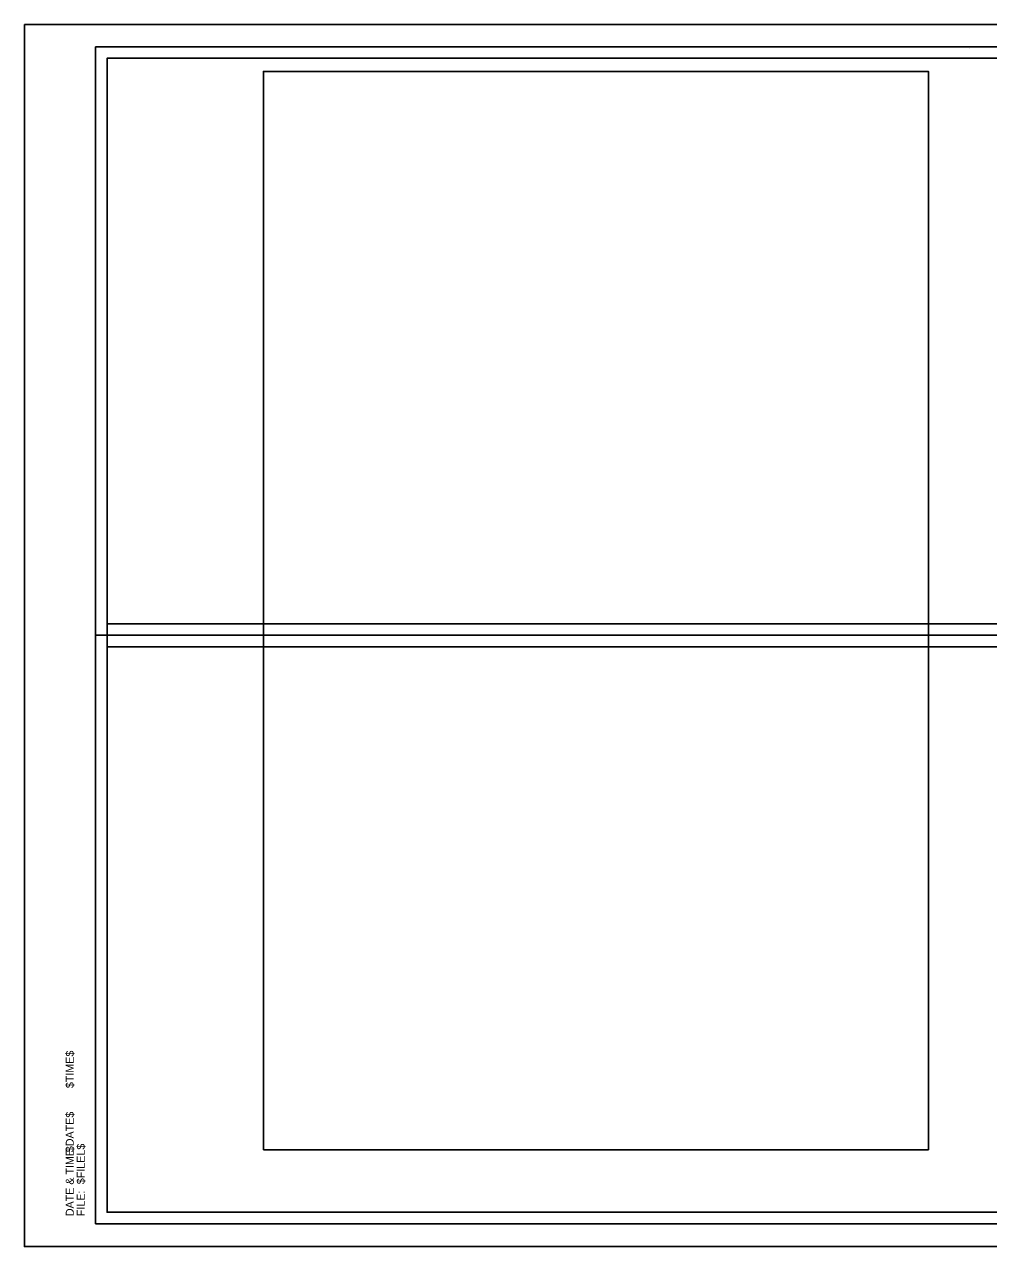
# Model space of a CAD drawing. Extents: x 1369940 to 1370273, y 380086 to 380299.
# Drawn here: x 1369939.7 to 1370108, y 380085.7 to 380299.1 of the extents above; entities that cross this region are included whole.
import ezdxf

# ---------------------------------------------------------------- set-up
doc = ezdxf.new("R2010")
doc.units = 0
for name, color, linetype in [('Default', 7, 'Continuous'), ('R_Border', 7, 'Continuous'), ('R_Border Notes', 7, 'Continuous'), ('R_Border Plan-Plan', 7, 'Continuous'), ('R_No Plot', 7, 'Continuous')]:
    doc.layers.add(name, color=color, linetype=linetype)

msp = doc.modelspace()

# ---------------------------------------------------------------- linework, layer by layer
at = {"layer": 'Default'}
msp.add_lwpolyline([(1369981.43, 380102.63), (1370097.49, 380102.63), (1370097.49, 380290.88), (1369981.43, 380290.88)], close=True, dxfattribs=at)
at = {"layer": 'R_Border'}
for p, q in [((1369952.12, 380295.18), (1370268.3, 380295.18)), ((1369952.12, 380089.72), (1369952.12, 380295.18)), ((1370104.64, 380294.92), (1370104.64, 380294.92)), ((1370104.64, 380294.92), (1370104.64, 380294.92)), ((1369952.12, 380089.72), (1369952.12, 380089.72)), ((1370268.3, 380089.72), (1369952.12, 380089.72))]:
    msp.add_line(p, q, dxfattribs=at)
at = {"layer": 'R_Border Plan-Plan'}
msp.add_line((1369952.12, 380192.45), (1370268.3, 380192.45), dxfattribs=at)
at = {"layer": 'R_No Plot'}
for points in [[(1369939.71, 380299.08), (1370273.05, 380299.08), (1370273.05, 380085.74), (1369939.71, 380085.74)], [(1370266.3, 380194.45), (1369954.12, 380194.45), (1369954.12, 380293.18), (1370203.66, 380293.18), (1370203.66, 380283.3), (1370221.2, 380283.3), (1370245.3, 380283.3), (1370245.3, 380260.97), (1370266.3, 380260.97)], [(1369954.12, 380293.18), (1370203.66, 380293.18), (1370203.66, 380283.3), (1370221.2, 380283.3), (1370245.3, 380283.3), (1370245.3, 380260.97), (1370266.3, 380260.97), (1370266.3, 380091.72), (1369954.12, 380091.72)], [(1369954.12, 380190.45), (1370266.3, 380190.45), (1370266.3, 380091.72), (1369954.12, 380091.72)]]:
    msp.add_lwpolyline(points, close=True, dxfattribs=at)

# ---------------------------------------------------------------- texts
at = {"layer": 'R_Border Notes'}
for s, height, p in [('$TIME$', 1.397, (1369948.32, 380113.4)), ('$DATE$', 1.397, (1369948.32, 380102.22)), ('$FILEL$', 1.397, (1369950.24, 380096.63)), ('DATE & TIME:', 1.3968, (1369948.32, 380091.05)), ('FILE: ', 1.397, (1369950.24, 380091.05))]:
    msp.add_text(s, height=height, rotation=90, dxfattribs=at).set_placement(p)

doc.saveas('drawing.dxf')
